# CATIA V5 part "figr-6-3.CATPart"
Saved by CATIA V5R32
Part number: Part1
Bounding box of the stored display mesh (mm): x -62.5 to 62.5, y -75 to 75, z 0 to 10
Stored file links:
  D:\PROJECTS\Project 2022\CATIA V5 6R 2022\Resources\Part Files\c06_catia_v5_6r2022_prt\figr-6-3.CATPart
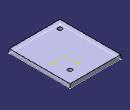
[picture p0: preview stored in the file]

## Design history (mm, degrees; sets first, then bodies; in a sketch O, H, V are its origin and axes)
Body1 (main body)
  Sketch1 on xy-plane, origin (0, 0, 0), H (1, 0, 0), V (0, 1, 0)
    line L1 (-62.5, 75) -> (62.5, 75)
    line L2 (62.5, 75) -> (62.5, -75)
    line L3 (62.5, -75) -> (-62.5, -75)
    line L4 (-62.5, -75) -> (-62.5, 75)
    axis line L5 (62.5, -75) -> (-62.5, 75)
    length L2 = 150
    length L3 = 125
    horizontal: L1 H, L3 H
    vertical: L2 V, L4 V
    midpoint: O L5
  Pad1: profile Sketch1, direction (0, 0, 1), length 10
  Sketch2 on face of Pad1, origin (-17.8347, -51.2044, 10), H (1, 0, 0), V (0, 1, 0)
    point P1 (-24.6653, -3.7956)
    reference projected line E1 (-44.6653, -23.7956) -> (80.3347, -23.7956) from edge [face of Pad1 | face of Pad1]
    reference projected line E2 (-44.6653, 126.2044) -> (-44.6653, -23.7956) from edge [face of Pad1 | face of Pad1]
    distance P1 E1 = 20
    distance P1 E2 = 20
  Hole1: placed by Sketch2, at (-42.5, -55, 10) direction (0, 0, -1), diameter 10, through (limit type 3)
  Sketch3 on face of Pad1, origin (35.5503, 42.9865, 10), H (1, 0, 0), V (0, 1, 0)
    point P1 (-3.0503, 2.0135)
    reference projected line E1 (26.9497, -117.9865) -> (26.9497, 32.0135) from edge [face of Pad1 | face of Pad1]
    reference projected line E2 (26.9497, 32.0135) -> (-98.0503, 32.0135) from edge [face of Pad1 | face of Pad1]
    distance P1 E1 = 30
    distance P1 E2 = 30
  Hole2: placed by Sketch3, at (32.5, 45, 10) direction (0, 0, -1), diameter 10, through (limit type 3)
